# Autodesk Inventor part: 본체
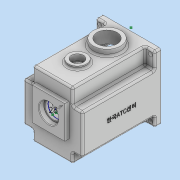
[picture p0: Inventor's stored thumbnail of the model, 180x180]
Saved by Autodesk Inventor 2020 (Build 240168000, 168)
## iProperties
Created: 2022-01
Part Number: 본체
Material: 일반
Document SubType Name: Modeling
Designer: user
Density: 1 g/cm^3
Appearance: 기본값
Author: user
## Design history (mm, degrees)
sketch "스케치1"
  geometry: 1 further point
sketch "스케치2"
  geometry: L1 (-49, 55)-(49, 55); L2 (49, 55)-(49, -55); L3 (49, -55)-(-49, -55); L4 (-49, -55)-(-49, 55); L5 (-49, 55)-(49, -55); L6 (49, 55)-(-49, -55); 1 further point
  constraints: 12 end point, 2 midpoint, 2 parallel, 1 horizontal, 1 perpendicular
  dimensions: "d0" = 98 distance of L2.end L3.end; "d1" = 110 distance of L1.end L2.end
extrude "돌출1" new body sketch "스케치2" distance "d2" = 10; taper "d3" = 0 deg
sketch "스케치3"
  geometry: L1 (49, -55)-(49, 55) reference; L2 (49, 55)-(-49, 55) reference; L3 (-49, 55)-(-49, -55) reference; L4 (-49, -55)-(49, -55) reference; L5 (49, -55)-(49, 55) reference; L6 (49, 55)-(33, 55); L7 (33, 55)-(33, 28); L8 (33, 28)-(49, 28); L9 (49, 28)-(49, 55); L10 (49, -55)-(33, -55); L11 (33, -55)-(33, -38); L12 (33, -38)-(49, -38); L13 (49, -38)-(49, -55); L14 (-49, -55)-(49, -55) reference; L15 (-49, -55)-(-33, -55); L16 (-33, -55)-(-33, -38); L17 (-33, -38)-(-49, -38); L18 (-49, -38)-(-49, -55); L19 (-49, 55)-(-49, -55) reference; L20 (-49, 55)-(-33, 55); L21 (-33, 55)-(-33, 28); L22 (-33, 28)-(-49, 28); L23 (-49, 28)-(-49, 55); 9 further points
  constraints: 32 end point, 8 parallel, 4 horizontal, 4 perpendicular, 1 point on line
  dimensions: "d4" = 27 distance of L6.end L7.end; "d5" = 16 distance of L7.end L8.end; "d6" = 17 distance of L10.end L11.end; "d7" = 16 distance of L11.end L12.end; "d8" = 27 distance of L20.end L21.end; "d9" = 16 distance of L21.end L22.end; "d10" = 16 distance of L16.end L17.end
extrude "돌출2" join sketch "스케치3" distance "d11" = 120; taper "d12" = 0 deg
sketch "스케치4"
  geometry: 1 further point
sketch "스케치5"
  geometry: L1 (49, -55)-(-49, -55) reference; L2 (-26, 48)-(26, 48); L3 (26, 48)-(26, 27.588); L4 (26, 27.588)-(-26, 27.588); L5 (-26, 27.588)-(-26, 48); C1 r 45 at (0, -5); 3 further points
  constraints: 8 end point, 2 parallel, 1 centre point, 1 horizontal, 1 perpendicular, 1 vertical alignment
  dimensions: "d13" = 90 diameter of C1; "d14" = 50 distance from line of L1 C1.centre; "d15" = 53 distance from line of L2 C1.centre; "d16" = 52 distance of L2.start L2.end; "d17" = 26 horizontal distance of C1.centre L2.start
extrude "돌출3" cut sketch "스케치5" distance "d18" = 9; taper "d19" = 0 deg
sketch "스케치6" dims "d27" = 8, "d28" = 8
  geometry: L1 (-26, 31.729)-(-26, 48) reference; L2 (26, 48)-(26, 31.729) reference; L3 (-26, 48)-(26, 48) reference; L4 (-23, 45)-(23, 45); L5 (23, 45)-(23, 21.058); L6 (23, 21.058)-(-23, 21.058); L7 (-23, 21.058)-(-23, 45); L8 (-35.778, -1.006)-(-41.81, -1.006); L9 (-35.778, -8.994)-(-41.81, -8.994); L10 (35.778, -1.006)-(42, -1.006); L11 (35.778, -8.994)-(41.81, -8.994); A1 r 45 centre (0, -5) between (-26, 31.729) and (26, 31.729) reference; A2 r 36 centre (0, -5) between (36, -5) and (-36, -5); A3 r 42 centre (0, -5) between (-41.81, -8.994) and (41.81, -8.994); A4 r 42 centre (0, -5) between (41.81, -1.006) and (-41.81, -1.006); 7 further points
  constraints: 16 end point, 10 point on circle, 4 horizontal, 3 centre point, 2 coincident, 2 horizontal alignment, 2 parallel, 1 perpendicular, 1 point on line, 6 other
  dimensions: "d21" = 46 distance of L4.start L4.end; "d22" = 23 distance from line of A1.centre L7; "d23" = 50 distance from line of A1.centre L4; "d26" = 72 diameter of A2
  node "투영된 루프2"
extrude "돌출4" cut sketch "스케치6" distance "d29" = 112; taper "d30" = 0 deg
fillet "모깎기1" dims "d31" = 3
sketch "스케치8"
  geometry: L1 (98, 0)-(0, 0) reference; C1 r 22.5 at (49, -40); C2 r 15 at (49, -89); 2 further points
  constraints: 2 centre point, 2 vertical alignment, 1 midpoint
  dimensions: "d32" = 45 diameter of C1; "d33" = 30 diameter of C2; "d34" = 40 distance of C1.centre point (49, 0); "d35" = 49 distance of C1.centre C2.centre
extrude "돌출5" join sketch "스케치8" distance "d36" = 10; taper "d37" = 0 deg
sketch "스케치9"
  geometry: C1 r 22.5 at (49, -40) reference; C2 r 15 at (49, -89); 1 further point
  constraints: 1 centre point, 1 vertical alignment
  dimensions: "d38" = 30 diameter of C2; "d39" = 49 distance of C1.centre C2.centre
extrude "돌출6" join sketch "스케치9" distance "d40" = 5; taper "d41" = 0 deg
sketch "스케치10"
  geometry: 1 further point
sketch "스케치11"
  geometry: C1 r 21 at (0, 6); C2 r 15 at (0, -25); C3 r 42 at (0, -5); A1 r 42 centre (0, -5) between (-23, 30.143) and (-41.319, 2.532) reference; 3 further points
  constraints: 3 centre point, 2 vertical alignment, 1 coincident
  dimensions: "d42" = 42 diameter of C1; "d43" = 30 diameter of C2; "d44" = 20 distance of C2.centre C3.centre; "d45" = 11 distance of C1.centre C3.centre
sketch "스케치12"
  geometry: C1 r 22.5 at (0, 0) reference; 2 further points
  constraints: 1 coincident
hole "구멍1" sketch "스케치12" at (0, 0) diameter "d46" = 33.376; stored, may be unused: countersink angle "d50" = 90 deg, drill point angle "d52" = 118 deg; dims "d47" = 70, "d48" = 4, "d49" = 2, "d51" = 77.3
extrude "돌출7" join sketch "스케치11" distance "d53" = 7; taper "d54" = 0 deg
sketch "스케치13"
  geometry: C1 r 11 at (0, -25); A1 r 15 centre (0, -25) between (-8.978, -12.984) and (8.978, -12.984) reference; 1 further point
  constraints: 1 centre point, 1 coincident
  dimensions: "d55" = 22 diameter of C1
extrude "돌출8" cut sketch "스케치13" distance "d56" = 7; taper "d57" = 0 deg
sketch "스케치14"
  geometry: C1 r 17.5 at (0, 6); A1 r 21 centre (0, 6) between (8.978, -12.984) and (-8.978, -12.984) reference; 1 further point
  constraints: 1 centre point, 1 coincident
  dimensions: "d58" = 35 diameter of C1
extrude "돌출9" cut sketch "스케치14" distance "d59" = 10; taper "d60" = 0 deg
sketch "스케치15"
  geometry: C1 r 11 at (0, 0) reference; C2 r 9.5 at (0, 0); 1 further point
  constraints: 1 centre point, 1 coincident
  dimensions: "d61" = 19 diameter of C2
extrude "돌출10" cut sketch "스케치15" distance "d62" = 3; taper "d63" = 0 deg
sketch "스케치16"
  geometry: C1 r 17.5 at (0, 0) reference; C2 r 14 at (0, 0); 1 further point
  constraints: 1 centre point, 1 coincident
  dimensions: "d64" = 28 diameter of C2
sketch "스케치17"
  geometry: 1 further point
sketch "스케치18"
  geometry: 1 further point
sketch "스케치19"
  geometry: L1 (-27, 33)-(27, 33); L2 (27, 33)-(27, -21); L3 (27, -21)-(-27, -21); L4 (-27, -21)-(-27, 33); L5 (-27, 33)-(27, -21); L6 (27, 33)-(-27, -21); 4 further points
  constraints: 12 end point, 3 midpoint, 2 parallel, 1 coincident, 1 horizontal, 1 perpendicular
  dimensions: "d65" = 54 distance of L2.end L3.end; "d66" = 54 distance of L1.end L2.end
extrude "돌출11" join sketch "스케치19" distance "d67" = 7; taper "d68" = 0 deg
sketch "스케치20"
  geometry: C1 r 16 at (0, 6); A1 r 21 centre (0, 6) between (8.978, -12.984) and (-8.978, -12.984) reference; 1 further point
  constraints: 1 centre point, 1 coincident
  dimensions: "d69" = 32 diameter of C1
extrude "돌출12" cut sketch "스케치20" distance "d70" = 8.3; taper "d71" = 0 deg
sketch "스케치21"
  geometry: C1 r 16 at (0, 0) reference; C2 r 14 at (0, 0); 1 further point
  constraints: 1 centre point, 1 coincident
  dimensions: "d72" = 28 diameter of C2
extrude "돌출13" cut sketch "스케치21" distance "d73" = 8.3; taper "d74" = 0 deg
sketch "스케치22"
  geometry: 1 further point
sketch "스케치23"
  geometry: C1 r 15 at (23, 80) reference; C2 r 15 at (23, 80); 1 further point
  constraints: 1 centre point, 1 coincident
  dimensions: "d75" = 30 diameter of C2
extrude "돌출14" cut sketch "스케치23" distance "d76" = 5; taper "d77" = 0 deg
sketch "스케치24"
  geometry: C1 r 15 at (0, 0) reference; C2 r 10 at (0, 0); 1 further point
  constraints: 1 centre point, 1 coincident
  dimensions: "d78" = 20 diameter of C2
extrude "돌출15" cut sketch "스케치24" stored distance "d79" = 5; taper "d80" = 0 deg
sketch "스케치25"
  geometry: L1 (33, -55)-(49, -55) reference; L2 (49, -55)-(49, -38) reference; L3 (-49, -38)-(-49, -55) reference; L4 (-49, -55)-(-33, -55) reference; L5 (-33, 55)-(-49, 55) reference; L6 (-49, 55)-(-49, 28) reference; L7 (49, 55)-(33, 55) reference; L8 (49, 28)-(49, 55) reference; C1 r 3.5 at (42, -48); C2 r 3.5 at (-42, -48); C3 r 3.5 at (-42, 48); C4 r 3.5 at (42, 48); 1 further point
  constraints: 4 centre point
  dimensions: "d81" = 7 diameter of C1; "d82" = 7 diameter of C2; "d83" = 7 diameter of C3; "d84" = 7 diameter of C4; "d85" = 7 distance from line of L1 C1.centre; "d86" = 7 distance from line of L2 C1.centre; "d87" = 7 distance from line of L3 C2.centre; "d88" = 7 distance from line of L4 C2.centre; "d89" = 7 distance from line of L5 C3.centre; "d90" = 7 distance from line of L6 C3.centre; "d91" = 7 distance from line of L7 C4.centre; "d92" = 7 distance from line of L8 C4.centre
extrude "돌출16" cut sketch "스케치25" distance "d93" = 10; taper "d94" = 0 deg
sketch "스케치26"
  geometry: A1 r 4 centre (-36, -5) between (-36.222, -8.994) and (-36.222, -1.006) reference; A2 r 4 centre (36, -5) between (36.222, -1.006) and (36.222, -8.994) reference; 3 further points
  constraints: 2 coincident
hole "구멍2" sketch "스케치26" at (-36, -5), (36, -5) diameter "d95" = 3.242; stored, may be unused: countersink angle "d99" = 90 deg, drill point angle "d101" = 118 deg; dims "d96" = 7, "d97" = 4, "d98" = 2, "d100" = 9
fillet "모깎기2" dims "d102" = 6
fillet "모깎기3" dims "d103" = 6
fillet "모깎기4" dims "d104" = 3
chamfer "모따기1" distance "d105" = 1; stored, may be unused: second distance "d106" = 2, angle "d107" = 45 deg
fillet "모깎기5" dims "d108" = 3
fillet "모깎기6" dims "d109" = 0.3
chamfer "모따기2" distance "d110" = 1; stored, may be unused: second distance "d111" = 2, angle "d112" = 45 deg
fillet "모깎기7" dims "d113" = 0.3
chamfer "모따기3" distance "d114" = 1; stored, may be unused: second distance "d115" = 2, angle "d116" = 45 deg
fillet "모깎기8" dims "d117" = 3
fillet "모깎기9" dims "d118" = 3
fillet "모깎기10" dims "d119" = 3
fillet "모깎기11" dims "d120" = 3
fillet "모깎기12" dims "d121" = 3
fillet "모깎기13" dims "d122" = 3
sketch "스케치27"
  geometry: 1 further point
fillet "모깎기14" dims "d123" = 3
sketch "스케치28"
  geometry: 1 further point
sketch "스케치29"
  geometry: L1 (-3, 60)-(-3, 0) reference; L2 (114, 90)-(0, 90) reference; 2 further points
  constraints: 1 other
  dimensions: "d124" = 65 distance from line of L1 point (62, 30); "d125" = 60 distance from line of L2 point (62, 30)
feature "엠보싱1" sketch "스케치29" dims "d4" = 27, "d5" = 16, "d126" = 0.5, "d127" = 0
node "솔리드1"
node "투영된 루프1"
node "투영된 루프3"
feature "A9D066F2-1C7D-4E18-AEED-F7BC21143FA4" dims "d46" = 33.376, "d47" = 70, "d48" = 4, "d49" = 2, "d50" = 90 deg, "d51" = 77.3, "d52" = 118 deg
other parameters: "d20" = 84
